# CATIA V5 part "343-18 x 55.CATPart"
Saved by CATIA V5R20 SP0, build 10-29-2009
Part number: 343-18 x 55
Definition: NONE
Nomenclature: 343-18 x 55
Source: Unknown
Description: 343-18 x 55
Bounding box of the stored display mesh (mm): x 0 to 55, y -14 to 14, z -14 to 14
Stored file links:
  C:\Users\Utente\Desktop\IO LAVORO\3D X SITO CF\X SITO\343-348\343-18 x 55.CATPart
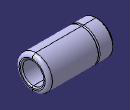
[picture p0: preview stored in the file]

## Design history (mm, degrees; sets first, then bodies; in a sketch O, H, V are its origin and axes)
Body1 "343-18 x 55" (main body)
  Solid1: solid without history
